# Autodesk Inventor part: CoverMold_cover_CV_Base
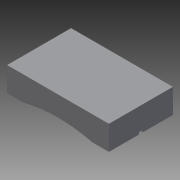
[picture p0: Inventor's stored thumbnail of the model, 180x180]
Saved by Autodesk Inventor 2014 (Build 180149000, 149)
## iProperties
Created: 2009-12
Part Number: CoverMold_cover_CV_Base
Document SubType Name: Modeling
Designer: gaom
Density: 1 g/cm^3
Material: Generic
Appearance: Default
Author: gaom
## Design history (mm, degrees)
node "CoverMold_cover_MP"
feature "Sculpt6"
feature "Solid4::CoverMold_cover_MP"
tag "TaggingFeature1"
body "Solid1"
feature "Surface6"
body "Srf6"
